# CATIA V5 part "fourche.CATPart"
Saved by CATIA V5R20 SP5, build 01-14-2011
Part number: fourche
Publications: "Longueur_fourche_1", "Longueur_fourche_2", "dent_fourche"
Bounding box of the stored display mesh (mm): x 0 to 5, y 0 to 79.445, z -8.409 to 147.388
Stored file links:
  E:\IAO_2010\iao\IAO_MMS_Groupe3\PB\jpeguet\jpeguet_IAO\jpeguet_IAO\fourche.CATPart
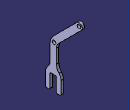
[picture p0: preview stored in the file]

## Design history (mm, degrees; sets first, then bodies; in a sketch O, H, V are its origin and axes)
Parameters
  dent_fourche = 30 mm
  Longueur_fourche_1 = 30 mm
  Longueur_fourche_2 = 70 mm
Body1 (main body)
  Sketch1 on yz-plane, origin (0, 0, 0), H (0, 1, 0), V (0, 0, 1)
    point P1 (0, 20)
    arc A1 centre (17.4, 20) radius 17.4 from (0, 20) to (4.8, 32) cw
    arc A2 centre (-7.9784, 44.1699) radius 17.6463 from (4.8, 32) to (9.668, 44.1699) ccw
    line L1 (9.668, 44.1699) -> (9.668, 75.6679)
    arc A3 centre (38.2579, 75.6679) radius 28.5899 from (9.668, 75.6679) to (18.0417, 95.884) cw
    point P7 (38.2579, 75.6679)
    line L2 (18.0417, 95.884) -> (67.5392, 145.3814)
    arc A4 centre (72.489, 140.4317) radius 7 from (67.5392, 145.3814) to (77.4387, 135.4819) cw
    line L3 (23.668, 75.6679) -> (23.668, 45.6679)
    arc A5 centre (44.3498, 45.6679) radius 20.6819 from (23.668, 45.6679) to (29.1189, 31.6765) ccw
    arc A6 centre (16.4079, 20) radius 17.2601 from (29.1189, 31.6765) to (33.668, 20) cw
    point P16 (33.668, 20)
    line L4 (33.668, 20) -> (33.668, -8.4093)
    line L5 (33.668, -8.4093) -> (23.668, -8.4093)
    line L6 (23.668, -8.4093) -> (23.668, 21.5907)
    line L7 (21.668, 23.5907) -> (11.668, 23.5907)
    line L8 (9.668, 21.5907) -> (9.668, -8.4093)
    arc A7 centre (38.2579, 75.6679) radius 14.5899 from (27.9412, 85.9845) to (23.668, 75.6679) ccw
    point P22 (38.2579, 75.6679)
    arc A8 centre (21.668, 21.5907) radius 2 from (23.668, 21.5907) to (21.668, 23.5907) ccw
    arc A9 centre (11.668, 21.5907) radius 2 from (11.668, 23.5907) to (9.668, 21.5907) ccw
    line L9 (27.9412, 85.9845) -> (77.4387, 135.4819)
    reference intersected line E1 through (0, 0) direction (-1, 0) from xy-plane
    reference intersected line E2 through (0, 0) direction (-1, 0) from xy-plane
    line L10 (0, 20) -> (0, -8.4093)
    line L11 (0, -8.4093) -> (9.668, -8.4093)
    radius A8 = 2
    radius A9 = 2
    length L8 = 30 {= dent_fourche}
    length L5 = 10
    length L7 = 10
    length L3 = 30 {= Longueur_fourche_1}
    length L9 = 70 {= Longueur_fourche_2}
    distance P1 E1 = 20
    distance P16 E2 = 20
    angle L9 L3 = 135
    tangency: A2 A1, A3 L1, A4 L2, A5 L3, A6 A5, A7 L3, A8 L6, A8 L7, A9 L7, A9 L8, A2 L1, A3 L2, L9 A7, L9 A4, A6 L4, L10 A1
    horizontal: L7 H, L5 H, L11 H
    vertical: L6 V, L8 V, L4 V, L1 V, L3 V, L10 V
    coincidence: L8 L1, L6 L3, P7 P22, L5 L11
    parallelism: L9 L2
  Pad1: profile Sketch1, direction (1, 0, 0), length 5
  Sketch2 on end face of Pad1, origin (5, 20.3108, 84.8108), H (0, 1, 0), V (0, 0, 1)
    point P1 (-1.7951, -0.9655)
    construction line L1 (-8.9723, -5.5295) -> (36.3458, 39.7886)
    reference projected line E1 (34.6622, 48.0045) -> (6.378, 19.7202) from edge [face of Pad1 from Sketch1.L2 | end face of Pad1]
    reference projected line E2 (34.6622, 48.0045) -> (6.378, 19.7202) from edge [face of Pad1 from Sketch1.L2 | end face of Pad1]
    construction line L2 (-3.6429, -33.4067) -> (-3.6429, 10.0355)
    reference projected line E3 (3.3571, -39.8108) -> (3.3571, -9.8108) from edge [face of Pad1 from Sketch1.L3 | end face of Pad1]
    point P6 (-3.6429, -0.2001)
    construction line L3 (-3.6429, -0.2001) -> (4.5974, -3.6134)
    distance L1 E2 = 7
    distance L2 E3 = 7
    angle L3 L1 = 67.5
    distance P1 P6 = 2
    parallelism: L1 E1
    vertical: L2 V
    coincidence: P6 L2, P6 L1, P1 L3
  Hole1: placed by Sketch2, at (5, 18.5157, 83.8453) direction (-1, 0, 0), diameter 8, through (limit type 3)
  Sketch3 on end face of Pad1, origin (5, 67.5979, 110.077), H (0, 1, 0), V (0, 0, 1)
    point P1 (4.8911, 30.3547)
    reference projected arc E1 centre (4.8911, 30.3547) radius 7 from (7.6462, 23.9197) to (2.1359, 36.7897) ccw from edge [face of Pad1 from Sketch1.A4 | end face of Pad1]
    concentricity: E1 P1
  Hole2: placed by Sketch3, at (5, 72.489, 140.4317) direction (-1, 0, 0), diameter 8, through (limit type 3)
  Fillet1: radius 2, on edge [face of Pad1 from Sketch1.L11 | face of Pad1 from Sketch1.L10]; edge [face of Pad1 from Sketch1.L8 | face of Pad1 from Sketch1.L11]; edge [face of Pad1 from Sketch1.L5 | face of Pad1 from Sketch1.L6]; edge [face of Pad1 from Sketch1.L4 | face of Pad1 from Sketch1.L5]
  Sketch4 on start face of Pad1, origin (0, 0, 0), H (0, -1, 0), V (0, 0, 1)
    line L1 (-16.668, 23.5907) -> (-16.668, -8.4093)
    point P1 (-16.668, 23.5907)
    point P2 (-16.668, -8.4093)
    reference projected line E1 (-9.668, -8.4093) -> (-9.668, 21.5907) from edge [start face of Pad1 | face of Pad1 from Sketch1.L8]
    reference projected line E2 (-11.668, 23.5907) -> (-21.668, 23.5907) from edge [start face of Pad1 | face of Pad1 from Sketch1.L7]
    reference projected line E3 (0, -8.4093) -> (-9.668, -8.4093) from edge [start face of Pad1 | face of Pad1 from Sketch1.L11]
    distance L1 E1 = 7
    distance P1 E2 = 0
    distance P2 E3 = 0
    vertical: L1 V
